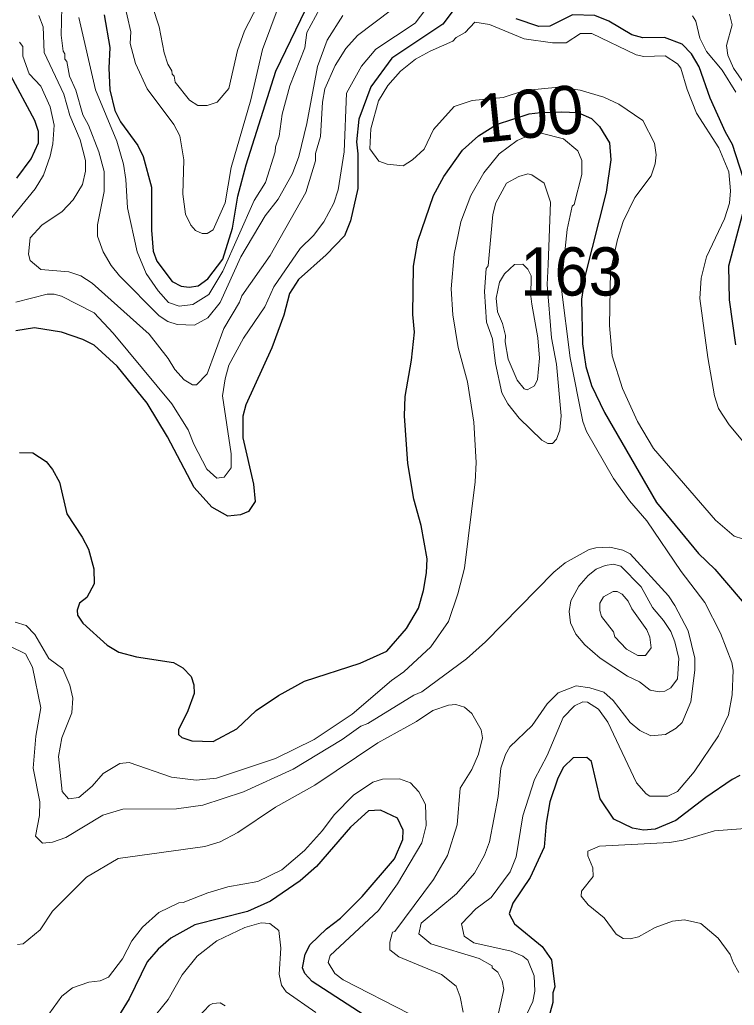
# Model space of a CAD drawing. Extents: x 673.3 to 698.5, y 6984.3 to 7012.3.
# Drawn here: x 687.685 to 688.869, y 6990.189 to 6991.822 of the extents above; entities that cross this region are included whole.
import ezdxf
from ezdxf.enums import TextEntityAlignment as Align

# ---------------------------------------------------------------- set-up
doc = ezdxf.new("R2010")
doc.units = 0
doc.header["$LTSCALE"] = 0.032
doc.layers.add('1', color=7, linetype='Continuous', lineweight=25)
doc.layers.add('2', color=7, linetype='Continuous', lineweight=13)
doc.layers.add('21', color=7, linetype='Continuous')
doc.layers.add('61', color=7, linetype='Continuous')

msp = doc.modelspace()

# ---------------------------------------------------------------- linework, layer by layer
at = {"layer": '1'}
for points in [[(687.8249, 6991.8299), (687.834, 6991.7758), (687.8324, 6991.742), (687.834, 6991.7057), (687.8423, 6991.6719), (687.8521, 6991.6531), (687.8806, 6991.6139), (687.8897, 6991.5954), (687.9033, 6991.5445), (687.9033, 6991.4734), (687.9061, 6991.4386), (687.9123, 6991.4218), (687.9377, 6991.3885), (687.9524, 6991.3804), (687.9659, 6991.379), (687.9807, 6991.381), (687.9966, 6991.3925), (688.0213, 6991.4254), (688.0375, 6991.4767), (688.0465, 6991.5295), (688.0599, 6991.5814), (688.1094, 6991.7367), (688.2174, 6991.9608)], [(688.4096, 6991.8461), (688.3863, 6991.8149), (688.3013, 6991.7581), (688.2668, 6991.711), (688.247, 6991.6574), (688.2429, 6991.62), (688.2452, 6991.5999), (688.2452, 6991.5426), (688.2331, 6991.4891), (688.2229, 6991.464), (688.1929, 6991.4324), (688.1467, 6991.3919), (688.1317, 6991.3682), (688.1224, 6991.3327), (688.1025, 6991.2785), (688.0595, 6991.1839), (688.0547, 6991.1651), (688.0546, 6991.1291), (688.0721, 6991.0526), (688.0749, 6991.0238), (688.0638, 6991.0073), (688.0507, 6991.0017), (688.0297, 6990.9994), (688.0032, 6991.0144), (687.9738, 6991.0471), (687.93, 6991.1308), (687.8963, 6991.1866), (687.8465, 6991.2483), (687.808, 6991.2831), (687.7895, 6991.2923), (687.7541, 6991.3045), (687.7094, 6991.3114), (687.6785, 6991.3064)], [(688.8837, 6991.5605), (688.8659, 6991.6153), (688.8543, 6991.6357), (688.8293, 6991.6921), (688.8107, 6991.7439), (688.7982, 6991.7657), (688.7825, 6991.7813), (688.7537, 6991.7925), (688.7176, 6991.7918), (688.6994, 6991.7971), (688.6613, 6991.8194), (688.6378, 6991.8292), (688.6007, 6991.83), (688.5635, 6991.8116)], [(688.5635, 6991.8116), (688.5449, 6991.8106), (688.5075, 6991.8235)], [(687.68, 6991.5596), (687.7036, 6991.5918), (687.7159, 6991.6179), (687.7159, 6991.637), (687.7101, 6991.6552), (687.6697, 6991.7304)], [(687.763, 6991.0032), (687.7886, 6990.9648), (687.7988, 6990.9451), (687.8079, 6990.9122), (687.8083, 6990.8875), (687.796, 6990.8646), (687.784, 6990.8554), (687.7803, 6990.8438), (687.7806, 6990.8353), (687.7894, 6990.8225), (687.8296, 6990.7859), (687.8492, 6990.774), (687.8785, 6990.7665), (687.9399, 6990.7569), (687.9553, 6990.7485), (687.9691, 6990.7339), (687.9732, 6990.72), (687.974, 6990.7058), (687.9637, 6990.6768), (687.9481, 6990.6454), (687.948, 6990.638), (687.9535, 6990.6327), (687.9701, 6990.6273), (688.0056, 6990.6265), (688.0447, 6990.6474), (688.0769, 6990.6779), (688.1138, 6990.7023), (688.1567, 6990.7262), (688.2492, 6990.7561), (688.2935, 6990.7759), (688.3258, 6990.8137), (688.3455, 6990.8474), (688.3543, 6990.8764), (688.3592, 6990.9057), (688.36, 6990.9288), (688.3503, 6990.9842), (688.338, 6991.0279), (688.328, 6991.0866), (688.3226, 6991.1656), (688.3235, 6991.1976), (688.3341, 6991.2582), (688.3389, 6991.3045), (688.3365, 6991.3335), (688.3375, 6991.4138), (688.3447, 6991.4549), (688.3705, 6991.5308), (688.3879, 6991.5624), (688.4185, 6991.6058), (688.445, 6991.6299), (688.475, 6991.6484), (688.5294, 6991.6662), (688.5479, 6991.6681), (688.5824, 6991.6697), (688.61, 6991.6684), (688.6326, 6991.6584), (688.6456, 6991.6453), (688.6622, 6991.6182), (688.6646, 6991.5901), (688.6566, 6991.5363), (688.6217, 6991.3986), (688.6159, 6991.3589), (688.6175, 6991.2849), (688.6232, 6991.2474), (688.6325, 6991.2163), (688.6539, 6991.1715), (688.74, 6991.0224), (688.8096, 6990.9375), (688.8366, 6990.912), (688.9014, 6990.8361)], [(688.8715, 6991.2836), (688.861, 6991.3578), (688.8602, 6991.4142), (688.8846, 6991.5054)], [(687.6843, 6991.105), (687.7066, 6991.1044), (687.7286, 6991.0899), (687.7393, 6991.0768), (687.7509, 6991.0557), (687.763, 6991.0032)], [(688.8783, 6990.5697), (688.8656, 6990.5635), (688.8221, 6990.5337), (688.7724, 6990.4954), (688.7378, 6990.4809), (688.7189, 6990.4791), (688.7004, 6990.4829), (688.6695, 6990.4978), (688.6468, 6990.5312), (688.6322, 6990.5933), (688.6245, 6990.5996), (688.602, 6990.5994), (688.5863, 6990.5837), (688.5764, 6990.5654), (688.5636, 6990.5262), (688.5572, 6990.4912), (688.5539, 6990.4514), (688.5308, 6990.4011), (688.5019, 6990.3587), (688.4962, 6990.3409), (688.5049, 6990.3243), (688.5506, 6990.2868), (688.5662, 6990.2644), (688.5718, 6990.2196), (688.5686, 6990.2099)], [(688.2949, 6990.1475), (688.1698, 6990.2289), (688.1576, 6990.2418), (688.1533, 6990.2511), (688.1578, 6990.2742), (688.1661, 6990.2898), (688.1931, 6990.3161), (688.2164, 6990.3337), (688.2522, 6990.3695), (688.3059, 6990.432), (688.32, 6990.4641), (688.3201, 6990.4793), (688.3112, 6990.4993), (688.2827, 6990.5124), (688.2631, 6990.5114), (688.2328, 6990.4844), (688.1767, 6990.4194), (688.1494, 6990.3953), (688.1005, 6990.3619), (688.0622, 6990.3444), (687.9751, 6990.3227), (687.9355, 6990.3002), (687.9142, 6990.2824), (687.8962, 6990.2613), (687.8662, 6990.1999), (687.8488, 6990.1714)], [(688.5686, 6990.2099), (688.5685, 6990.1939), (688.5614, 6990.1679)]]:
    msp.add_lwpolyline(points, dxfattribs=at)
at = {"layer": '2'}
for points in [[(688.1965, 6991.8678), (688.1609, 6991.8009), (688.1572, 6991.7755), (688.1326, 6991.7127), (688.12, 6991.6653), (688.115, 6991.6292), (688.1086, 6991.6113), (688.1084, 6991.6029), (688.0921, 6991.5523), (688.0735, 6991.5224), (688.0213, 6991.4055), (687.9983, 6991.3669), (687.9719, 6991.3505), (687.9492, 6991.3473), (687.9316, 6991.3538), (687.9145, 6991.3729), (687.8947, 6991.4014), (687.8797, 6991.4377), (687.8634, 6991.5104), (687.8608, 6991.5575), (687.8568, 6991.583), (687.846, 6991.621), (687.8102, 6991.706), (687.7827, 6991.8258)], [(688.0944, 6991.8754), (688.0574, 6991.8038), (688.0458, 6991.7709), (688.0314, 6991.708), (688.0119, 6991.6856), (687.9956, 6991.6797), (687.98, 6991.6802), (687.9662, 6991.689), (687.9425, 6991.7185), (687.9406, 6991.7287), (687.9374, 6991.7316), (687.9372, 6991.7374), (687.9306, 6991.7484), (687.9243, 6991.7673), (687.9161, 6991.81), (687.9047, 6991.8442)], [(687.7419, 6991.3674), (687.754, 6991.364), (687.8085, 6991.3367), (687.8399, 6991.3029), (687.9367, 6991.1857), (687.9639, 6991.1425), (687.9732, 6991.1191), (687.9949, 6991.0773), (688.0113, 6991.0626), (688.0239, 6991.0642), (688.0351, 6991.0798), (688.0351, 6991.1031), (688.0212, 6991.1989), (688.0251, 6991.2272), (688.0315, 6991.2499), (688.0559, 6991.2945), (688.091, 6991.3465), (688.1058, 6991.3795), (688.1499, 6991.4432), (688.1716, 6991.4648), (688.189, 6991.4872), (688.2052, 6991.5179), (688.2125, 6991.5403), (688.2224, 6991.6029), (688.2265, 6991.7002), (688.2513, 6991.7451), (688.2753, 6991.773), (688.3405, 6991.8163), (688.3686, 6991.8531)], [(687.8566, 6991.8556), (687.8688, 6991.8018), (687.8678, 6991.7824), (687.877, 6991.7497), (687.8963, 6991.7077), (687.9405, 6991.6487), (687.9504, 6991.6294), (687.9569, 6991.5898), (687.9553, 6991.5332)], [(687.9553, 6991.5332), (687.9597, 6991.5), (687.9682, 6991.4818), (687.9762, 6991.4729), (687.9874, 6991.4678), (687.9957, 6991.4677), (688.0053, 6991.4738), (688.0253, 6991.5184), (688.0352, 6991.5771), (688.0677, 6991.6894), (688.0873, 6991.7725), (688.1147, 6991.8465)], [(687.7549, 6991.8427), (687.7533, 6991.7967), (687.7567, 6991.7698), (687.7598, 6991.7657), (687.7599, 6991.7569), (687.7631, 6991.7527), (687.7675, 6991.7283), (687.7778, 6991.7052), (687.7893, 6991.6647), (687.7988, 6991.6471), (687.8161, 6991.6034), (687.8249, 6991.5708), (687.825, 6991.5377), (687.8136, 6991.4822), (687.8139, 6991.4632), (687.8231, 6991.4373), (687.8363, 6991.415), (687.8502, 6991.3977), (687.9161, 6991.3314), (687.9306, 6991.322), (687.9458, 6991.3173), (687.9745, 6991.3162), (687.9968, 6991.3284), (688.0171, 6991.3534), (688.0513, 6991.4291), (688.0916, 6991.4969), (688.1133, 6991.5247), (688.1369, 6991.5671), (688.1475, 6991.5956), (688.1605, 6991.6501), (688.1785, 6991.7445), (688.1946, 6991.7883), (688.2206, 6991.829)], [(688.301, 6991.8385), (688.2444, 6991.7958), (688.2252, 6991.7741), (688.2079, 6991.7464), (688.1904, 6991.7078), (688.1866, 6991.6853), (688.1832, 6991.6284), (688.1752, 6991.6004), (688.1751, 6991.5883), (688.1588, 6991.5359), (688.1001, 6991.4316), (688.0532, 6991.3645), (688.0492, 6991.3542), (688.0233, 6991.3104), (687.9954, 6991.2352), (687.9778, 6991.2169), (687.9711, 6991.2169), (687.9573, 6991.2253), (687.9418, 6991.2423), (687.9308, 6991.2608), (687.8996, 6991.3011), (687.8052, 6991.3855), (687.7859, 6991.3976)], [(688.9032, 6991.6908), (688.868, 6991.7417), (688.8584, 6991.7631), (688.8561, 6991.7793), (688.8658, 6991.8134), (688.8612, 6991.831)], [(687.7859, 6991.3976), (687.7664, 6991.4041), (687.72, 6991.4082), (687.702, 6991.4232), (687.6996, 6991.4337), (687.702, 6991.4609), (687.7215, 6991.4815), (687.7551, 6991.5044), (687.7736, 6991.5236), (687.789, 6991.5489), (687.7941, 6991.5709), (687.7939, 6991.5888), (687.7853, 6991.6229), (687.768, 6991.6634), (687.7582, 6991.6989), (687.7256, 6991.7676), (687.724, 6991.81), (687.7166, 6991.8292)], [(688.883, 6991.1241), (688.8606, 6991.151), (688.843, 6991.1779), (688.8365, 6991.1988), (688.825, 6991.2627), (688.812, 6991.3601), (688.8144, 6991.394), (688.8231, 6991.4291), (688.8526, 6991.4919), (688.8609, 6991.5181), (688.8626, 6991.5385), (688.8601, 6991.5699), (688.8437, 6991.6096), (688.8066, 6991.6674), (688.7911, 6991.7065), (688.7807, 6991.7418), (688.7749, 6991.749), (688.7547, 6991.7624), (688.719, 6991.7609), (688.7065, 6991.764), (688.6329, 6991.799), (688.6144, 6991.799), (688.5905, 6991.7837), (688.5676, 6991.7838), (688.5208, 6991.7901), (688.4632, 6991.8143), (688.4393, 6991.8178), (688.423, 6991.8011), (688.4082, 6991.7924), (688.4026, 6991.7863), (688.3652, 6991.7702), (688.3408, 6991.7566), (688.3157, 6991.7368), (688.2948, 6991.7133), (688.2796, 6991.6878), (688.2666, 6991.6412), (688.265, 6991.6081), (688.2802, 6991.5875), (688.2937, 6991.5826), (688.3202, 6991.5802), (688.3359, 6991.5899), (688.3549, 6991.6076), (688.3705, 6991.6401), (688.4051, 6991.6785), (688.4345, 6991.6884), (688.486, 6991.6933), (688.5216, 6991.705), (688.5775, 6991.7103), (688.6139, 6991.7053), (688.653, 6991.6938), (688.6777, 6991.6824), (688.7173, 6991.655), (688.7371, 6991.6175), (688.7396, 6991.5984), (688.7379, 6991.5831), (688.7313, 6991.5635), (688.7041, 6991.5276), (688.6852, 6991.4878), (688.6753, 6991.4582), (688.6639, 6991.4057), (688.6621, 6991.3152), (688.6669, 6991.265), (688.6837, 6991.211), (688.7088, 6991.1563), (688.7354, 6991.1118), (688.8379, 6990.993), (688.8687, 6990.9666), (688.9244, 6990.9488)], [(688.7996, 6991.8283), (688.8056, 6991.8197), (688.8121, 6991.7916), (688.8232, 6991.7694), (688.8489, 6991.7386), (688.8717, 6991.702)], [(687.6846, 6991.7846), (687.6898, 6991.7776), (687.69, 6991.7618), (687.7005, 6991.7325), (687.7199, 6991.7119), (687.7354, 6991.6777), (687.7418, 6991.6471), (687.7396, 6991.6164), (687.7354, 6991.5961), (687.7243, 6991.5643), (687.7103, 6991.542), (687.6513, 6991.4699)], [(688.8657, 6990.7035), (688.8675, 6990.7443), (688.865, 6990.7572), (688.8465, 6990.8059), (688.8203, 6990.8566), (688.7812, 6990.9079), (688.7242, 6990.9918), (688.6957, 6991.0252), (688.6687, 6991.0621), (688.6241, 6991.14), (688.6183, 6991.1563), (688.5971, 6991.262), (688.5823, 6991.3801), (688.5919, 6991.4745), (688.6005, 6991.5134), (688.6038, 6991.516), (688.6165, 6991.5654), (688.6165, 6991.5888), (688.6099, 6991.6047), (688.586, 6991.6248), (688.549, 6991.6341), (688.5296, 6991.631), (688.5093, 6991.6221), (688.4794, 6991.6), (688.4541, 6991.5684), (688.4324, 6991.5309), (688.4157, 6991.4871), (688.4048, 6991.4334), (688.4001, 6991.376), (688.4026, 6991.333), (688.4113, 6991.279), (688.4267, 6991.2223), (688.4374, 6991.1552), (688.4414, 6991.0884), (688.4398, 6991.0566), (688.4221, 6990.9133), (688.4112, 6990.8709), (688.3955, 6990.8253), (688.3663, 6990.7833), (688.3215, 6990.7415), (688.3009, 6990.7275), (688.236, 6990.6718), (688.1726, 6990.6298), (688.109, 6990.5981), (688.011, 6990.5654), (687.9771, 6990.5621), (687.9364, 6990.5671), (687.866, 6990.5913), (687.8509, 6990.5899), (687.8232, 6990.5732), (687.8052, 6990.552), (687.7827, 6990.5336), (687.7656, 6990.5312), (687.755, 6990.5437), (687.7493, 6990.6013), (687.7546, 6990.6326), (687.7711, 6990.6738), (687.7728, 6990.6978), (687.7682, 6990.7194), (687.7566, 6990.7467), (687.7332, 6990.7639), (687.7097, 6990.8037), (687.6954, 6990.8184), (687.6774, 6990.8241)], [(687.6782, 6991.3543), (687.7305, 6991.3674), (687.7419, 6991.3674)], [(687.6686, 6990.7843), (687.6945, 6990.7714), (687.7061, 6990.7493), (687.7199, 6990.682), (687.7118, 6990.6353), (687.707, 6990.5822), (687.7183, 6990.5262), (687.7175, 6990.5035), (687.711, 6990.4695), (687.7228, 6990.458), (687.739, 6990.4595), (687.7612, 6990.4674), (687.8225, 6990.5042), (687.8559, 6990.5139), (687.9445, 6990.5149), (687.9882, 6990.5206), (688.0557, 6990.5428), (688.1379, 6990.5804), (688.2195, 6990.6298), (688.2502, 6990.6516), (688.2618, 6990.6559), (688.3379, 6990.7028), (688.3512, 6990.7088), (688.4252, 6990.763), (688.4568, 6990.7914), (688.5698, 6990.907), (688.5889, 6990.922), (688.6286, 6990.9442), (688.6395, 6990.9472), (688.6628, 6990.948), (688.6844, 6990.9433), (688.6964, 6990.9374), (688.7599, 6990.8674), (688.7708, 6990.8515), (688.7924, 6990.8096), (688.8038, 6990.7643)], [(688.8038, 6990.7643), (688.8038, 6990.7443), (688.7973, 6990.6921), (688.7826, 6990.658), (688.7727, 6990.6482), (688.7553, 6990.6379), (688.7309, 6990.6354), (688.7125, 6990.6444), (688.6968, 6990.658), (688.6684, 6990.6943), (688.6527, 6990.708), (688.6299, 6990.7151), (688.6068, 6990.7184), (688.5771, 6990.7067), (688.559, 6990.6888), (688.534, 6990.6529), (688.497, 6990.6176), (688.4897, 6990.6047), (688.4824, 6990.5822), (688.478, 6990.5354), (688.4636, 6990.46), (688.4552, 6990.4381), (688.4386, 6990.4079), (688.4087, 6990.3737), (688.3501, 6990.3253), (688.3464, 6990.3078), (688.3664, 6990.291), (688.4462, 6990.2668), (688.4681, 6990.2544), (688.4681, 6990.2513), (688.4774, 6990.2441), (688.4845, 6990.2297), (688.4872, 6990.2152), (688.4782, 6990.1763)], [(688.5195, 6990.1628), (688.5351, 6990.1956), (688.5384, 6990.2129), (688.5377, 6990.2381), (688.527, 6990.2639), (688.5185, 6990.2707), (688.4991, 6990.2787), (688.4374, 6990.2926), (688.4212, 6990.3039), (688.4171, 6990.324), (688.441, 6990.349), (688.4663, 6990.3679), (688.4975, 6990.4104), (688.5075, 6990.4353), (688.5188, 6990.5031), (688.5378, 6990.5632), (688.5589, 6990.603), (688.5853, 6990.6663), (688.6043, 6990.6852), (688.618, 6990.6922), (688.6261, 6990.6916), (688.6438, 6990.6797), (688.6596, 6990.6584), (688.7072, 6990.5579), (688.7232, 6990.5393), (688.729, 6990.5358), (688.7589, 6990.5357), (688.7748, 6990.5435), (688.8024, 6990.5761), (688.8429, 6990.6354), (688.8594, 6990.6705), (688.8657, 6990.7035)], [(687.6812, 6990.2901), (687.6905, 6990.2913), (687.7186, 6990.314), (687.7391, 6990.3451), (687.7955, 6990.4014), (687.8479, 6990.4325), (687.9914, 6990.4522), (688.0169, 6990.4601), (688.0461, 6990.4757), (688.1087, 6990.5174), (688.1739, 6990.5541), (688.2781, 6990.6241), (688.3427, 6990.6596), (688.3697, 6990.6779), (688.3952, 6990.6866), (688.4078, 6990.6874), (688.4221, 6990.6833), (688.4342, 6990.6726), (688.4494, 6990.6458), (688.452, 6990.6321), (688.4453, 6990.6054), (688.4341, 6990.5801), (688.4147, 6990.549), (688.4096, 6990.4881), (688.3937, 6990.4373), (688.3708, 6990.3978), (688.3063, 6990.3115), (688.3024, 6990.3103), (688.2982, 6990.2936), (688.2984, 6990.281), (688.3134, 6990.2698), (688.3841, 6990.2405), (688.4079, 6990.221), (688.4147, 6990.2034), (688.4195, 6990.1779)], [(687.7187, 6990.1545), (687.7544, 6990.2044), (687.7724, 6990.218), (687.7992, 6990.2274), (687.8182, 6990.2297), (687.8318, 6990.2358), (687.8553, 6990.2663), (687.8708, 6990.2963), (687.8881, 6990.3189), (687.9155, 6990.3429), (687.9483, 6990.359), (687.956, 6990.3595), (687.9969, 6990.3758), (688.03, 6990.3853), (688.0797, 6990.3945), (688.1195, 6990.4134), (688.1566, 6990.4458), (688.1869, 6990.4786), (688.2058, 6990.5047), (688.2378, 6990.5374), (688.2703, 6990.559), (688.2862, 6990.5637), (688.3142, 6990.5643), (688.3323, 6990.5578), (688.3465, 6990.543), (688.3576, 6990.5218), (688.3584, 6990.4871), (688.3513, 6990.4583), (688.3109, 6990.3905), (688.2793, 6990.3463), (688.1993, 6990.2718), (688.1963, 6990.2603), (688.207, 6990.2421), (688.2211, 6990.2312), (688.3308, 6990.175)], [(688.9014, 6990.483), (688.8363, 6990.4781), (688.7844, 6990.4626), (688.7618, 6990.4587), (688.6459, 6990.4529), (688.6264, 6990.4445), (688.6264, 6990.4367), (688.6345, 6990.4171), (688.6353, 6990.4028), (688.616, 6990.3783), (688.6153, 6990.3701), (688.6269, 6990.3554), (688.6532, 6990.334), (688.6732, 6990.3069), (688.6851, 6990.2999), (688.6964, 6990.2995), (688.7105, 6990.3029), (688.7378, 6990.3181), (688.7667, 6990.3284), (688.7866, 6990.3307), (688.8138, 6990.3248), (688.8422, 6990.3007), (688.8625, 6990.2735), (688.867, 6990.2601), (688.8768, 6990.2433)], [(688.1755, 6990.1775), (688.1267, 6990.2116), (688.1186, 6990.2227), (688.115, 6990.241), (688.1174, 6990.284), (688.1141, 6990.3134), (688.0993, 6990.325), (688.085, 6990.3258), (688.058, 6990.3179), (688.0116, 6990.2962), (687.9789, 6990.2704), (687.9541, 6990.2399), (687.931, 6990.1991), (687.9005, 6990.1611)], [(687.9522, 6990.1395), (687.9995, 6990.1896), (688.0047, 6990.1923), (688.0171, 6990.1931), (688.0253, 6990.1881)]]:
    msp.add_lwpolyline(points, dxfattribs=at)
for points in [[(688.5128, 6991.1619), (688.4938, 6991.1857), (688.484, 6991.2041), (688.4733, 6991.2524), (688.4683, 6991.2934), (688.4586, 6991.3211), (688.4553, 6991.3719), (688.4578, 6991.4097), (688.4611, 6991.4145), (688.469, 6991.4992), (688.474, 6991.5185), (688.4918, 6991.5512), (688.5121, 6991.5624), (688.5267, 6991.5668), (688.5336, 6991.5652), (688.5538, 6991.5514), (688.5644, 6991.5197), (688.5607, 6991.4164), (688.5588, 6991.3834), (688.5661, 6991.295), (688.5742, 6991.2516), (688.5823, 6991.1658), (688.5799, 6991.1419), (688.5742, 6991.1272), (688.5677, 6991.1202), (688.5601, 6991.1198), (688.5501, 6991.1254)], [(688.5465, 6991.2611), (688.5433, 6991.2948), (688.5335, 6991.3509), (688.5321, 6991.3641), (688.5325, 6991.398), (688.527, 6991.4088), (688.5188, 6991.417), (688.5048, 6991.4164), (688.4881, 6991.401), (688.4799, 6991.3873), (688.4744, 6991.3607), (688.4764, 6991.3379), (688.4852, 6991.3185), (688.4902, 6991.2988), (688.4896, 6991.2883), (688.4943, 6991.2597), (688.5092, 6991.2247), (688.5211, 6991.2104), (688.5259, 6991.2087), (688.5379, 6991.2157), (688.5431, 6991.2258)], [(688.6067, 6990.8041), (688.5979, 6990.8226), (688.5955, 6990.8416), (688.5982, 6990.8595), (688.6112, 6990.8835), (688.6269, 6990.9014), (688.6403, 6990.9118), (688.6551, 6990.918), (688.6691, 6990.9202), (688.6812, 6990.9165), (688.7145, 6990.8827), (688.7337, 6990.8482), (688.7519, 6990.8269), (688.7637, 6990.8086), (688.7707, 6990.7912), (688.777, 6990.764), (688.7752, 6990.7301), (688.7638, 6990.7151), (688.7538, 6990.7096), (688.7444, 6990.7087), (688.7299, 6990.7114), (688.7118, 6990.7249), (688.6921, 6990.7343), (688.6467, 6990.7646), (688.6212, 6990.7863)], [(688.6993, 6990.846), (688.6931, 6990.8585), (688.683, 6990.8703), (688.6749, 6990.8747), (688.6684, 6990.8748), (688.6526, 6990.8658), (688.646, 6990.8557), (688.646, 6990.8434), (688.6493, 6990.8332), (688.6687, 6990.8079), (688.671, 6990.7994), (688.6905, 6990.779), (688.7092, 6990.7686), (688.7217, 6990.7689), (688.7314, 6990.7814), (688.7291, 6990.7992), (688.724, 6990.8113)]]:
    msp.add_lwpolyline(points, close=True, dxfattribs=at)

# ---------------------------------------------------------------- texts
at = {"layer": '21', "width": 0.95}
msp.add_text('163', height=0.08, dxfattribs=at).set_placement((688.5147, 6991.365))
at = {"layer": '61'}
msp.add_text('100', height=0.08, rotation=5.829, dxfattribs=at).set_placement((688.5339, 6991.6265), align=Align.CENTER)

doc.saveas('drawing.dxf')
